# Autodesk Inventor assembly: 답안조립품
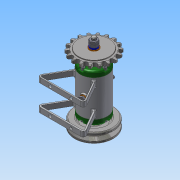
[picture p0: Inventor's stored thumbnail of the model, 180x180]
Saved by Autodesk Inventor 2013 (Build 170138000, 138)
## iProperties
Created: 2016-03
Part Number: 답안조립품
Document SubType Name: Assembly
Designer: Administrator
Author: Administrator
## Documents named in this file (16)
- C:\Users\Administrator\Desktop\460308V1025\답안조립품.iam
- C:\Users\Administrator\Desktop\460308V1025\본체.ipt
- C:\Users\Administrator\Desktop\460308V1025\V벨트풀리.ipt
- C:\Users\Administrator\Desktop\460308V1025\너트 M 8.ipt
- C:\Users\Administrator\Desktop\460308V1025\니플 M 6 x 0.75.ipt
- C:\Users\Administrator\Desktop\460308V1025\베어링 15 x 32 x 9.ipt
- C:\Users\Administrator\Desktop\460308V1025\볼트 M 6 x 8.ipt
- C:\Users\Administrator\Desktop\460308V1025\볼트 M4 x 12.ipt
- C:\Users\Administrator\Desktop\460308V1025\스프로킷.ipt
- C:\Users\Administrator\Desktop\460308V1025\스프링와셔 8.ipt
- C:\Users\Administrator\Desktop\460308V1025\오일 실 15 25 7.ipt
- C:\Users\Administrator\Desktop\460308V1025\와셔 6x11.5.ipt
- C:\Users\Administrator\Desktop\460308V1025\와셔 8x17.ipt
- C:\Users\Administrator\Desktop\460308V1025\축.ipt
- C:\Users\Administrator\Desktop\460308V1025\커버.ipt
- C:\Users\Administrator\Desktop\460308V1025\키 3 x 3 x 12.ipt
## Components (11 placed, 3 different names)
1. V벨트풀리:1
2. KS B 2023 6002 - 15 x 32 x 9:1
3. KS B 2023 6002 - 15 x 32 x 9:2
4. ISO 4762 M4 x 12:2
5. ISO 4762 M4 x 12:3
6. ISO 4762 M4 x 12:4
7. ISO 4762 M4 x 12:5
8. ISO 4762 M4 x 12:1
9. ISO 4762 M4 x 12:6
10. ISO 4762 M4 x 12:7
11. ISO 4762 M4 x 12:8
